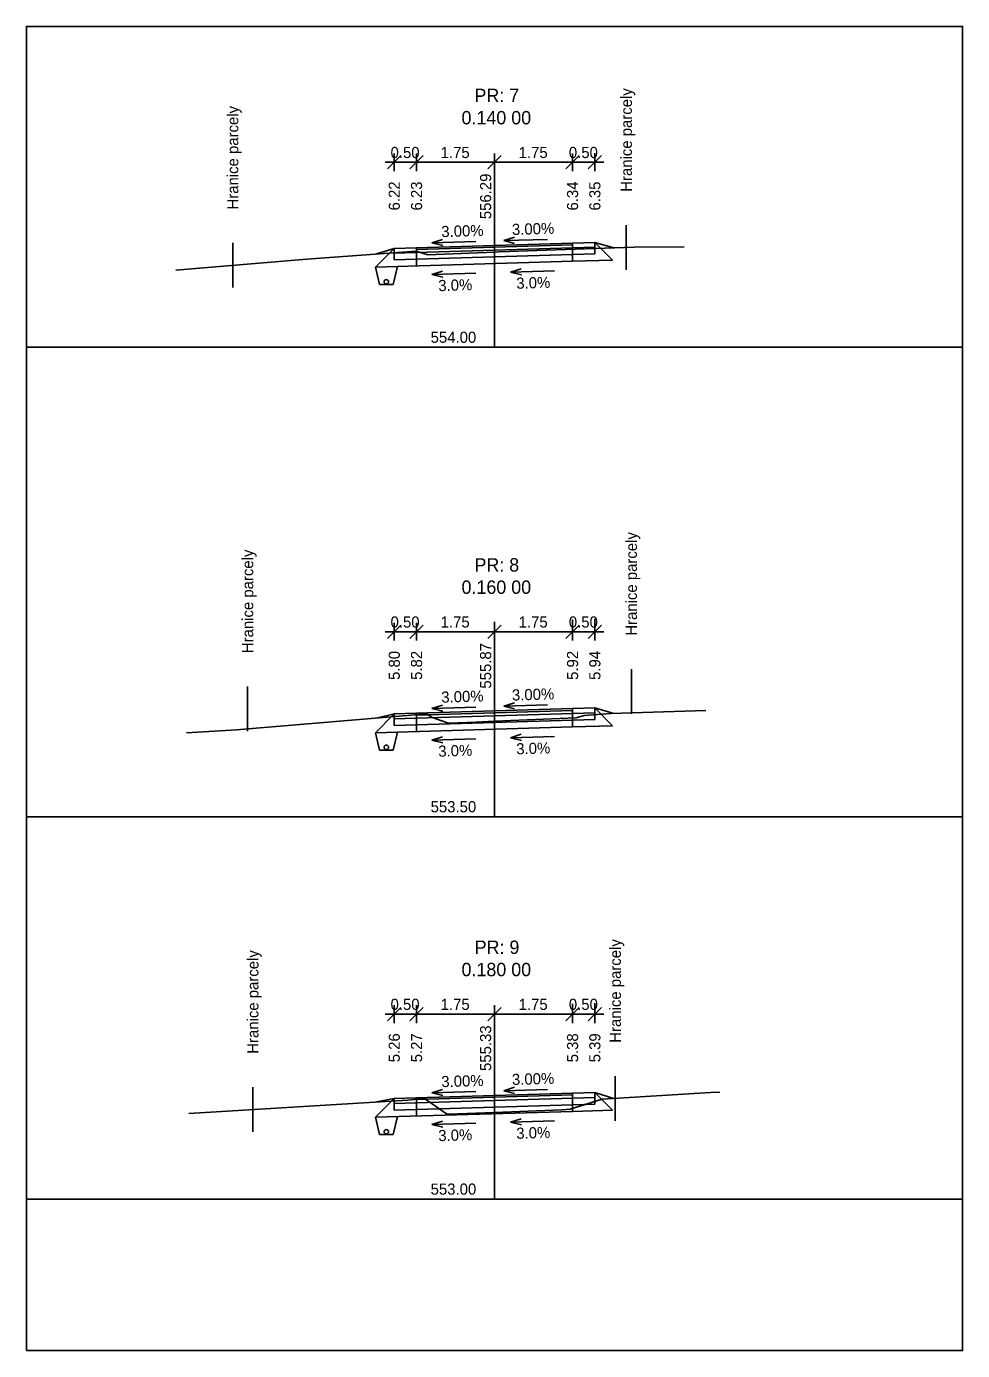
# Model space of a CAD drawing. Extents: x -603737 to -603383, y -1112154 to -1112124.
# Drawn here: x -603662.37 to -603641.37, y -1112153.84 to -1112124.14 of the extents above; entities that cross this region are included whole.
import ezdxf

# ---------------------------------------------------------------- set-up
doc = ezdxf.new("R2010")
doc.units = 0
for name, color, linetype in [('_křivky z hran', 7, 'Continuous'), ('_netisk', 7, 'Continuous'), ('C3D_Podsestava-Popis', 7, 'Continuous'), ('C3D_PP-Popisek', 7, 'Continuous'), ('C3D_PR', 7, 'Continuous'), ('C3D_ZPR', 7, 'Continuous'), ('Default', 7, 'Continuous'), ('konstrukce', 7, 'Continuous')]:
    doc.layers.add(name, color=color, linetype=linetype)

# ---------------------------------------------------------------- blocks, each defined once
blk = doc.blocks.new('_Oblique')
at = {"layer": 'Default'}
blk.add_line((-0.5, -0.5), (0.5, 0.5), dxfattribs=at)
blk = doc.blocks.new('AeccTickLine')
at = {"layer": 'Default'}
blk.add_line((0, 1), (0, -1), dxfattribs=at)

msp = doc.modelspace()

# ---------------------------------------------------------------- linework, layer by layer
at = {"layer": '_netisk'}
msp.add_lwpolyline([(-603662.373, -1112153.84), (-603641.373, -1112153.84), (-603641.373, -1112124.14), (-603662.373, -1112124.14)], close=True, dxfattribs=at)
at = {"layer": 'C3D_Podsestava-Popis'}
for p, q in [((-603654.323, -1112127.186), (-603651.873, -1112127.186)), ((-603654.123, -1112127.118), (-603654.123, -1112127.336)), ((-603653.623, -1112127.336), (-603653.623, -1112127.103)), ((-603651.873, -1112127.336), (-603651.873, -1112127.051)), ((-603651.873, -1112127.186), (-603649.423, -1112127.186)), ((-603650.123, -1112127.336), (-603650.123, -1112126.998)), ((-603649.623, -1112126.983), (-603649.623, -1112127.336)), ((-603654.123, -1112137.562), (-603654.123, -1112137.867)), ((-603653.623, -1112137.867), (-603653.623, -1112137.547)), ((-603651.873, -1112137.867), (-603651.873, -1112137.494)), ((-603650.123, -1112137.867), (-603650.123, -1112137.442)), ((-603649.623, -1112137.427), (-603649.623, -1112137.867)), ((-603654.323, -1112137.717), (-603651.873, -1112137.717)), ((-603651.873, -1112137.717), (-603649.423, -1112137.717)), ((-603654.123, -1112146.186), (-603654.123, -1112146.444)), ((-603653.623, -1112146.444), (-603653.623, -1112146.171)), ((-603651.873, -1112146.444), (-603651.873, -1112146.118)), ((-603650.123, -1112146.444), (-603650.123, -1112146.066)), ((-603649.623, -1112146.051), (-603649.623, -1112146.444)), ((-603654.323, -1112146.294), (-603651.873, -1112146.294)), ((-603651.873, -1112146.294), (-603649.423, -1112146.294))]:
    msp.add_line(p, q, dxfattribs=at)
at = {"layer": 'C3D_PP-Popisek'}
for p, q in [((-603653.276, -1112128.993), (-603653.04, -1112128.917)), ((-603652.292, -1112128.963), (-603653.276, -1112128.993)), ((-603651.665, -1112128.944), (-603651.428, -1112128.869)), ((-603650.681, -1112128.915), (-603651.665, -1112128.944)), ((-603651.665, -1112128.944), (-603651.424, -1112129.005)), ((-603653.276, -1112128.993), (-603653.035, -1112129.054)), ((-603653.276, -1112129.703), (-603653.04, -1112129.627)), ((-603652.292, -1112129.673), (-603653.276, -1112129.703)), ((-603653.276, -1112129.703), (-603653.035, -1112129.764)), ((-603651.512, -1112129.65), (-603651.275, -1112129.574)), ((-603650.528, -1112129.62), (-603651.512, -1112129.65)), ((-603651.512, -1112129.65), (-603651.271, -1112129.711)), ((-603653.276, -1112139.437), (-603653.04, -1112139.361)), ((-603651.665, -1112139.388), (-603651.428, -1112139.313)), ((-603650.681, -1112139.359), (-603651.665, -1112139.388)), ((-603652.292, -1112139.407), (-603653.276, -1112139.437)), ((-603653.276, -1112139.437), (-603653.035, -1112139.498)), ((-603651.665, -1112139.388), (-603651.424, -1112139.449)), ((-603653.276, -1112140.147), (-603653.04, -1112140.071)), ((-603652.292, -1112140.117), (-603653.276, -1112140.147)), ((-603653.276, -1112140.147), (-603653.035, -1112140.208)), ((-603651.512, -1112140.094), (-603651.275, -1112140.018)), ((-603650.528, -1112140.064), (-603651.512, -1112140.094)), ((-603651.512, -1112140.094), (-603651.271, -1112140.155)), ((-603651.665, -1112148.012), (-603651.428, -1112147.936)), ((-603653.276, -1112148.06), (-603653.04, -1112147.985)), ((-603652.292, -1112148.031), (-603653.276, -1112148.06)), ((-603653.276, -1112148.06), (-603653.035, -1112148.121)), ((-603650.681, -1112147.982), (-603651.665, -1112148.012)), ((-603651.665, -1112148.012), (-603651.424, -1112148.073)), ((-603653.276, -1112148.77), (-603653.04, -1112148.695)), ((-603652.292, -1112148.741), (-603653.276, -1112148.77)), ((-603653.276, -1112148.77), (-603653.035, -1112148.831)), ((-603651.512, -1112148.717), (-603651.275, -1112148.642)), ((-603650.528, -1112148.688), (-603651.512, -1112148.717)), ((-603651.512, -1112148.717), (-603651.271, -1112148.778))]:
    msp.add_line(p, q, dxfattribs=at)
at = {"layer": 'C3D_PR'}
for points in [[(-603659.024, -1112129.603), (-603656.082, -1112129.356), (-603653.629, -1112129.178), (-603653.372, -1112129.265), (-603651.873, -1112129.201), (-603651.775, -1112129.196), (-603650.283, -1112129.143), (-603648.74, -1112129.092), (-603647.62, -1112129.083)], [(-603658.782, -1112139.983), (-603657.661, -1112139.915), (-603653.393, -1112139.561), (-603653.274, -1112139.641), (-603652.908, -1112139.767), (-603652.294, -1112139.743), (-603651.873, -1112139.725), (-603650.041, -1112139.648), (-603649.864, -1112139.593), (-603649.263, -1112139.554), (-603647.135, -1112139.486)], [(-603658.73, -1112148.521), (-603653.822, -1112148.221), (-603653.446, -1112148.19), (-603652.947, -1112148.529), (-603652.916, -1112148.54), (-603651.873, -1112148.498), (-603650.361, -1112148.438), (-603650.175, -1112148.43), (-603649.461, -1112148.205), (-603647.026, -1112148.049), (-603646.821, -1112148.043)]]:
    msp.add_lwpolyline(points, dxfattribs=at)
at = {"layer": 'C3D_ZPR'}
for p, q in [((-603651.873, -1112131.336), (-603651.873, -1112127.336)), ((-603648.916, -1112129.598), (-603648.916, -1112128.598)), ((-603657.745, -1112129.996), (-603657.745, -1112128.996)), ((-603654.546, -1112129.541), (-603654.123, -1112129.118)), ((-603654.123, -1112129.118), (-603654.518, -1112129.243)), ((-603654.518, -1112129.243), (-603654.123, -1112129.118)), ((-603654.123, -1112129.228), (-603649.623, -1112129.093)), ((-603654.123, -1112129.118), (-603653.623, -1112129.103)), ((-603654.123, -1112129.378), (-603654.123, -1112129.118)), ((-603654.123, -1112129.378), (-603654.123, -1112129.118)), ((-603654.123, -1112129.228), (-603653.623, -1112129.213)), ((-603654.123, -1112129.378), (-603649.623, -1112129.243)), ((-603653.623, -1112129.103), (-603649.623, -1112128.983)), ((-603653.623, -1112129.143), (-603650.123, -1112129.038)), ((-603653.623, -1112129.513), (-603653.623, -1112129.103)), ((-603653.623, -1112129.213), (-603653.623, -1112129.143)), ((-603650.123, -1112129.038), (-603650.123, -1112128.998)), ((-603650.123, -1112129.408), (-603650.123, -1112128.998)), ((-603650.123, -1112129.108), (-603649.623, -1112129.093)), ((-603650.123, -1112129.258), (-603650.123, -1112129.108)), ((-603650.123, -1112129.258), (-603649.623, -1112129.243)), ((-603649.623, -1112129.243), (-603649.623, -1112128.983)), ((-603649.623, -1112129.243), (-603649.623, -1112128.983)), ((-603649.623, -1112128.983), (-603649.225, -1112129.381)), ((-603649.623, -1112128.983), (-603649.198, -1112129.107)), ((-603649.623, -1112128.983), (-603649.198, -1112129.107)), ((-603654.546, -1112129.541), (-603650.123, -1112129.408)), ((-603654.123, -1112129.378), (-603653.623, -1112129.363)), ((-603653.623, -1112129.513), (-603653.623, -1112129.363)), ((-603650.123, -1112129.408), (-603649.225, -1112129.381)), ((-603662.373, -1112131.336), (-603641.373, -1112131.336)), ((-603651.873, -1112141.867), (-603651.873, -1112137.867)), ((-603648.803, -1112139.555), (-603648.803, -1112138.555)), ((-603657.411, -1112139.947), (-603657.411, -1112138.947)), ((-603654.546, -1112139.985), (-603654.123, -1112139.562)), ((-603654.123, -1112139.562), (-603654.518, -1112139.654)), ((-603654.518, -1112139.654), (-603654.123, -1112139.562)), ((-603654.123, -1112139.672), (-603649.623, -1112139.537)), ((-603654.123, -1112139.562), (-603653.623, -1112139.547)), ((-603654.123, -1112139.822), (-603654.123, -1112139.562)), ((-603654.123, -1112139.822), (-603654.123, -1112139.562)), ((-603654.123, -1112139.672), (-603653.623, -1112139.657)), ((-603653.623, -1112139.547), (-603649.623, -1112139.427)), ((-603653.623, -1112139.587), (-603650.123, -1112139.482)), ((-603653.623, -1112139.957), (-603653.623, -1112139.547)), ((-603653.623, -1112139.657), (-603653.623, -1112139.587)), ((-603650.123, -1112139.482), (-603650.123, -1112139.442)), ((-603650.123, -1112139.852), (-603650.123, -1112139.442)), ((-603650.123, -1112139.552), (-603649.623, -1112139.537)), ((-603650.123, -1112139.702), (-603650.123, -1112139.552)), ((-603649.623, -1112139.687), (-603649.623, -1112139.427)), ((-603649.623, -1112139.687), (-603649.623, -1112139.427)), ((-603649.623, -1112139.427), (-603649.225, -1112139.825)), ((-603649.623, -1112139.427), (-603649.198, -1112139.552)), ((-603649.623, -1112139.427), (-603649.198, -1112139.552)), ((-603654.546, -1112139.985), (-603650.123, -1112139.852)), ((-603654.123, -1112139.822), (-603649.623, -1112139.687)), ((-603654.123, -1112139.822), (-603653.623, -1112139.807)), ((-603653.623, -1112139.957), (-603653.623, -1112139.807)), ((-603650.123, -1112139.702), (-603649.623, -1112139.687)), ((-603650.123, -1112139.852), (-603649.225, -1112139.825)), ((-603662.373, -1112141.867), (-603641.373, -1112141.867)), ((-603651.873, -1112150.444), (-603651.873, -1112146.444)), ((-603657.294, -1112148.933), (-603657.294, -1112147.933)), ((-603649.163, -1112148.686), (-603649.163, -1112147.686)), ((-603654.546, -1112148.608), (-603654.123, -1112148.186)), ((-603654.123, -1112148.186), (-603654.518, -1112148.264)), ((-603654.518, -1112148.264), (-603654.123, -1112148.186)), ((-603654.123, -1112148.296), (-603649.623, -1112148.161)), ((-603654.123, -1112148.186), (-603653.623, -1112148.171)), ((-603654.123, -1112148.446), (-603654.123, -1112148.186)), ((-603654.123, -1112148.446), (-603654.123, -1112148.186)), ((-603653.623, -1112148.171), (-603649.623, -1112148.051)), ((-603653.623, -1112148.211), (-603650.123, -1112148.106)), ((-603653.623, -1112148.581), (-603653.623, -1112148.171)), ((-603653.623, -1112148.281), (-603653.623, -1112148.211)), ((-603650.123, -1112148.106), (-603650.123, -1112148.066)), ((-603650.123, -1112148.476), (-603650.123, -1112148.066)), ((-603650.123, -1112148.176), (-603649.623, -1112148.161)), ((-603650.123, -1112148.326), (-603650.123, -1112148.176)), ((-603649.623, -1112148.311), (-603649.623, -1112148.051)), ((-603649.623, -1112148.311), (-603649.623, -1112148.051)), ((-603649.623, -1112148.051), (-603649.225, -1112148.449)), ((-603649.623, -1112148.051), (-603649.198, -1112148.188)), ((-603649.623, -1112148.051), (-603649.198, -1112148.188)), ((-603654.546, -1112148.608), (-603650.123, -1112148.476)), ((-603654.123, -1112148.296), (-603653.623, -1112148.281)), ((-603654.123, -1112148.446), (-603649.623, -1112148.311)), ((-603654.123, -1112148.446), (-603653.623, -1112148.431)), ((-603653.623, -1112148.581), (-603653.623, -1112148.431)), ((-603650.123, -1112148.326), (-603649.623, -1112148.311)), ((-603650.123, -1112148.476), (-603649.225, -1112148.449)), ((-603662.373, -1112150.444), (-603641.373, -1112150.444))]:
    msp.add_line(p, q, dxfattribs=at)
at = {"layer": 'konstrukce'}
for p, q in [((-603654.45, -1112129.926), (-603654.546, -1112129.541)), ((-603654.15, -1112129.926), (-603654.05, -1112129.526)), ((-603654.15, -1112129.926), (-603654.45, -1112129.926)), ((-603654.45, -1112140.37), (-603654.546, -1112139.985)), ((-603654.15, -1112140.37), (-603654.05, -1112139.97)), ((-603654.15, -1112140.37), (-603654.45, -1112140.37)), ((-603654.45, -1112148.993), (-603654.546, -1112148.608)), ((-603654.15, -1112148.993), (-603654.05, -1112148.593)), ((-603654.15, -1112148.993), (-603654.45, -1112148.993))]:
    msp.add_line(p, q, dxfattribs=at)
for centre in [(-603654.3, -1112129.866), (-603654.3, -1112140.31), (-603654.3, -1112148.933)]:
    msp.add_circle(centre, 0.05, dxfattribs=at)

# ---------------------------------------------------------------- block references
at = {"layer": '_křivky z hran', "rotation": 180}
for name, p, xscale, yscale in [('_Oblique', (-603654.123, -1112127.186), 0.3, 0.3), ('AeccTickLine', (-603654.123, -1112127.186), 0.2, 0.20000000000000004), ('_Oblique', (-603653.623, -1112127.186), 0.3, 0.3), ('AeccTickLine', (-603653.623, -1112127.186), 0.2, 0.20000000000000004), ('_Oblique', (-603651.873, -1112127.186), 0.3, 0.3), ('AeccTickLine', (-603651.873, -1112127.186), 0.2, 0.20000000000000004), ('_Oblique', (-603654.123, -1112137.717), 0.3, 0.3), ('AeccTickLine', (-603654.123, -1112137.717), 0.2, 0.20000000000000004), ('_Oblique', (-603653.623, -1112137.717), 0.3, 0.3), ('AeccTickLine', (-603653.623, -1112137.717), 0.2, 0.20000000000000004), ('_Oblique', (-603651.873, -1112137.717), 0.3, 0.3), ('AeccTickLine', (-603651.873, -1112137.717), 0.2, 0.20000000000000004), ('_Oblique', (-603654.123, -1112146.294), 0.3, 0.3), ('AeccTickLine', (-603654.123, -1112146.294), 0.2, 0.20000000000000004), ('_Oblique', (-603653.623, -1112146.294), 0.3, 0.3), ('AeccTickLine', (-603653.623, -1112146.294), 0.2, 0.20000000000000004), ('_Oblique', (-603651.873, -1112146.294), 0.3, 0.3), ('AeccTickLine', (-603651.873, -1112146.294), 0.2, 0.20000000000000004)]:
    msp.add_blockref(name, p, dxfattribs=dict(at, xscale=xscale, yscale=yscale))
at = {"layer": '_křivky z hran'}
for name, p, xscale, yscale in [('_Oblique', (-603651.873, -1112127.186), 0.3, 0.3), ('AeccTickLine', (-603651.873, -1112127.186), 0.2, 0.20000000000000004), ('_Oblique', (-603650.123, -1112127.186), 0.3, 0.3), ('AeccTickLine', (-603650.123, -1112127.186), 0.2, 0.20000000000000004), ('_Oblique', (-603649.623, -1112127.186), 0.3, 0.3), ('AeccTickLine', (-603649.623, -1112127.186), 0.2, 0.20000000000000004), ('_Oblique', (-603651.873, -1112137.717), 0.3, 0.3), ('AeccTickLine', (-603651.873, -1112137.717), 0.2, 0.20000000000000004), ('_Oblique', (-603650.123, -1112137.717), 0.3, 0.3), ('AeccTickLine', (-603650.123, -1112137.717), 0.2, 0.20000000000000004), ('_Oblique', (-603649.623, -1112137.717), 0.3, 0.3), ('AeccTickLine', (-603649.623, -1112137.717), 0.2, 0.20000000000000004), ('_Oblique', (-603651.873, -1112146.294), 0.3, 0.3), ('AeccTickLine', (-603651.873, -1112146.294), 0.2, 0.20000000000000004), ('_Oblique', (-603650.123, -1112146.294), 0.3, 0.3), ('AeccTickLine', (-603650.123, -1112146.294), 0.2, 0.20000000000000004), ('_Oblique', (-603649.623, -1112146.294), 0.3, 0.3), ('AeccTickLine', (-603649.623, -1112146.294), 0.2, 0.20000000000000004)]:
    msp.add_blockref(name, p, dxfattribs=dict(at, xscale=xscale, yscale=yscale))

# ---------------------------------------------------------------- texts
at = {"layer": 'C3D_Podsestava-Popis'}
for s, rotation, p in [('0.50', 360, (-603654.205, -1112127.092)), ('1.75', 360, (-603653.081, -1112127.092)), ('1.75', 360, (-603653.081, -1112127.092)), ('1.75', 360, (-603651.331, -1112127.092)), ('1.75', 360, (-603651.331, -1112127.092)), ('0.50', 360, (-603650.205, -1112127.092)), ('556.29', 90, (-603651.947, -1112128.463)), ('6.22', 90, (-603653.997, -1112128.267)), ('6.22', 90, (-603653.997, -1112128.267)), ('6.23', 90, (-603653.497, -1112128.268)), ('6.34', 90, (-603649.997, -1112128.268)), ('6.35', 90, (-603649.497, -1112128.269)), ('6.35', 90, (-603649.497, -1112128.269)), ('3.00%', 1.7184, (-603653.063, -1112128.866)), ('3.00%', 1.7184, (-603651.478, -1112128.818)), ('3.0%', 1.7184, (-603653.131, -1112130.078)), ('3.0%', 1.7184, (-603651.381, -1112130.025)), ('0.50', 360, (-603654.205, -1112137.623)), ('1.75', 360, (-603653.081, -1112137.623)), ('1.75', 360, (-603653.081, -1112137.623)), ('1.75', 360, (-603651.331, -1112137.623)), ('1.75', 360, (-603651.331, -1112137.623)), ('0.50', 360, (-603650.205, -1112137.623)), ('5.80', 90, (-603653.997, -1112138.798)), ('5.80', 90, (-603653.997, -1112138.798)), ('5.82', 90, (-603653.497, -1112138.797)), ('555.87', 90, (-603651.947, -1112138.993)), ('5.92', 90, (-603649.997, -1112138.797)), ('5.94', 90, (-603649.497, -1112138.798)), ('5.94', 90, (-603649.497, -1112138.798)), ('3.00%', 1.7184, (-603653.063, -1112139.31)), ('3.00%', 1.7184, (-603651.478, -1112139.262)), ('3.0%', 1.7184, (-603653.131, -1112140.522)), ('3.0%', 1.7184, (-603651.381, -1112140.469)), ('0.50', 360, (-603654.205, -1112146.2)), ('1.75', 360, (-603653.081, -1112146.2)), ('1.75', 360, (-603653.081, -1112146.2)), ('1.75', 360, (-603651.331, -1112146.2)), ('1.75', 360, (-603651.331, -1112146.2)), ('0.50', 360, (-603650.205, -1112146.2)), ('5.26', 90, (-603653.997, -1112147.375)), ('5.26', 90, (-603653.997, -1112147.375)), ('5.27', 90, (-603653.497, -1112147.375)), ('555.33', 90, (-603651.947, -1112147.57)), ('5.38', 90, (-603649.997, -1112147.376)), ('5.39', 90, (-603649.497, -1112147.376)), ('5.39', 90, (-603649.497, -1112147.376)), ('3.00%', 1.7184, (-603653.063, -1112147.934)), ('3.00%', 1.7184, (-603651.478, -1112147.886)), ('3.0%', 1.7184, (-603651.381, -1112149.093)), ('3.0%', 1.7184, (-603653.131, -1112149.145))]:
    msp.add_text(s, height=0.25, rotation=rotation, dxfattribs=at).set_placement(p)
at = {"layer": 'C3D_ZPR'}
for s, p in [('PR: 7', (-603652.323, -1112125.836)), ('0.140 00', (-603652.613, -1112126.336)), ('PR: 8', (-603652.323, -1112136.367)), ('0.160 00', (-603652.613, -1112136.867)), ('PR: 9', (-603652.318, -1112144.944)), ('0.180 00', (-603652.613, -1112145.444))]:
    msp.add_text(s, height=0.3, dxfattribs=at).set_placement(p)
for s, rotation, p in [('Hranice parcely', 90, (-603648.791, -1112127.848)), ('Hranice parcely', 90, (-603657.62, -1112128.246)), ('554.00', 360, (-603653.306, -1112131.236)), ('Hranice parcely', 90, (-603648.678, -1112137.805)), ('Hranice parcely', 90, (-603657.286, -1112138.197)), ('553.50', 360, (-603653.306, -1112141.767)), ('Hranice parcely', 90, (-603649.038, -1112146.936)), ('Hranice parcely', 90, (-603657.169, -1112147.183)), ('553.00', 360, (-603653.306, -1112150.344))]:
    msp.add_text(s, height=0.25, rotation=rotation, dxfattribs=at).set_placement(p)

doc.saveas('drawing.dxf')
